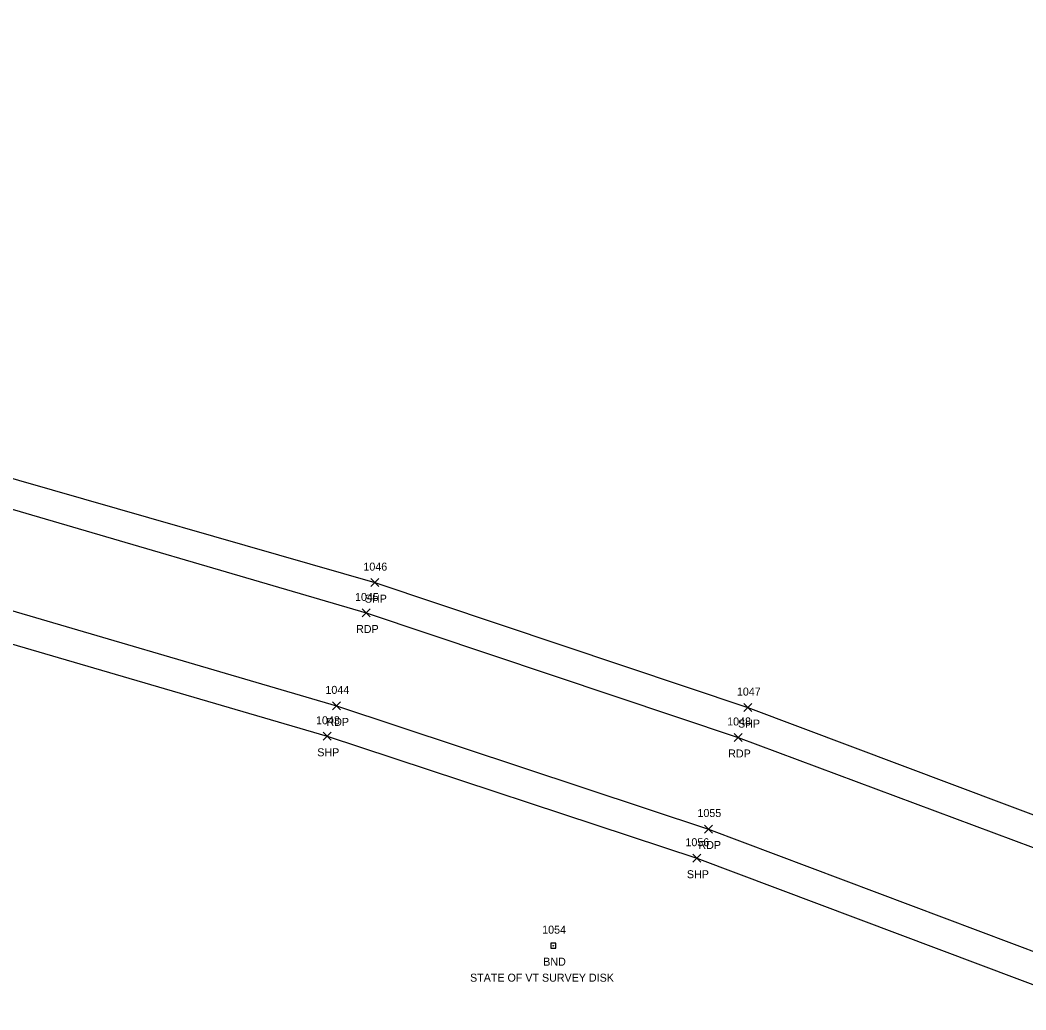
# Model space of a CAD drawing. Extents: x 1519347 to 1522636, y 378779 to 379832.
# Drawn here: x 1521349.9 to 1521601.3, y 379467.3 to 379714.6 of the extents above; entities that cross this region are included whole.
import ezdxf

# ---------------------------------------------------------------- set-up
doc = ezdxf.new("R2010")
doc.units = 0
for name, color, linetype in [('M_A', 7, 'Continuous'), ('M_C', 7, 'Continuous'), ('M_I', 7, 'Continuous'), ('MHBP', 7, 'Continuous'), ('P_A', 7, 'Continuous'), ('P_I', 7, 'Continuous'), ('P_TIC', 7, 'Continuous'), ('PE', 7, 'Continuous'), ('PSP', 7, 'Continuous')]:
    doc.layers.add(name, color=color, linetype=linetype)

msp = doc.modelspace()

# ---------------------------------------------------------------- linework, layer by layer
at = {"layer": 'MHBP'}
for p, q in [((1521483.81, 379483.95), (1521482.56, 379483.95)), ((1521482.56, 379483.95), (1521482.56, 379482.7)), ((1521483.81, 379483.95), (1521482.56, 379483.95)), ((1521482.56, 379483.95), (1521482.56, 379482.7)), ((1521483.81, 379482.7), (1521483.81, 379483.95)), ((1521483.81, 379482.7), (1521483.81, 379483.95)), ((1521482.56, 379482.7), (1521483.81, 379482.7)), ((1521482.56, 379482.7), (1521483.81, 379482.7))]:
    msp.add_line(p, q, dxfattribs=at)
msp.add_circle((1521483.16, 379483.29), 0.0833, dxfattribs=at)
at = {"layer": 'P_TIC'}
for points in [[(1521437.52, 379573.01), (1521439.52, 379575.01)], [(1521439.52, 379573.01), (1521437.52, 379575.01)], [(1521435.37, 379565.43), (1521437.37, 379567.43)], [(1521437.37, 379565.43), (1521435.37, 379567.43)], [(1521427.97, 379542.22), (1521429.97, 379544.22)], [(1521429.97, 379542.22), (1521427.97, 379544.22)], [(1521530.82, 379541.79), (1521532.82, 379543.79)], [(1521532.82, 379541.79), (1521530.82, 379543.79)], [(1521425.62, 379534.62), (1521427.62, 379536.62)], [(1521427.62, 379534.62), (1521425.62, 379536.62)], [(1521528.39, 379534.32), (1521530.39, 379536.32)], [(1521530.39, 379534.32), (1521528.39, 379536.32)], [(1521520.96, 379511.45), (1521522.96, 379513.45)], [(1521522.96, 379511.45), (1521520.96, 379513.45)], [(1521518.02, 379504.15), (1521520.02, 379506.15)], [(1521520.02, 379504.15), (1521518.02, 379506.15)]]:
    msp.add_lwpolyline(points, dxfattribs=at)
at = {"layer": 'PE'}
for points in [[(1520500.29, 379707.13), (1520597.92, 379701.55), (1520704.39, 379695.17), (1520766.67, 379691.18), (1520865.72, 379682.95), (1520944.87, 379673.83), (1521043.86, 379659.67), (1521144.22, 379641.18), (1521240.97, 379619.56), (1521339.55, 379594.81), (1521436.37, 379566.43), (1521529.39, 379535.32), (1521632.62, 379496.8)], [(1520499.12, 379683.2), (1520597.12, 379677.59), (1520702.85, 379672.1), (1520767.36, 379666.64), (1520862.37, 379658.78), (1520941.16, 379649.92), (1521039.54, 379635.66), (1521138.91, 379617.62), (1521235.57, 379596.13), (1521333.44, 379571.25), (1521428.97, 379543.22), (1521521.96, 379512.45), (1521622.97, 379474.43)]]:
    msp.add_lwpolyline(points, dxfattribs=at)
at = {"layer": 'PSP'}
for points in [[(1520500.66, 379714.58), (1520598.16, 379708.86), (1520704.83, 379702.57), (1520767.67, 379698.75), (1520866.58, 379691.1), (1520963.04, 379679.86), (1520962.98, 379679.81), (1521045.38, 379667.49), (1521145.9, 379649.23), (1521242.81, 379627.02), (1521341.58, 379601.87), (1521438.52, 379574.01), (1521531.82, 379542.79), (1521635.1, 379503.97)], [(1520498.56, 379673.83), (1520597.58, 379669.39), (1520622.82, 379668.23), (1520701.9, 379664.18), (1520764.8, 379659.6), (1520862, 379650.94), (1520940.1, 379642.46), (1521038.42, 379628.05), (1521137.18, 379609.65), (1521233.6, 379588.29), (1521331.39, 379563.44), (1521426.62, 379535.62), (1521519.02, 379505.15), (1521619.86, 379467.25)]]:
    msp.add_lwpolyline(points, dxfattribs=at)

# ---------------------------------------------------------------- texts
at = {"layer": 'M_A'}
msp.add_text('BND', height=2, dxfattribs=at).set_placement((1521480.64, 379478.3))
at = {"layer": 'M_C'}
msp.add_text('STATE OF VT SURVEY DISK', height=2, dxfattribs=at).set_placement((1521462.35, 379474.3))
at = {"layer": 'M_I'}
msp.add_text('1054', height=2, dxfattribs=at).set_placement((1521480.38, 379486.3))
at = {"layer": 'P_A'}
for s, p in [('SHP', (1521436.05, 379569.01)), ('RDP', (1521433.86, 379561.43)), ('RDP', (1521426.46, 379538.22)), ('SHP', (1521529.35, 379537.79)), ('SHP', (1521424.16, 379530.62)), ('RDP', (1521526.88, 379530.32)), ('RDP', (1521519.45, 379507.45)), ('SHP', (1521516.55, 379500.15))]:
    msp.add_text(s, height=2, dxfattribs=at).set_placement(p)
at = {"layer": 'P_I'}
for s, p in [('1046', (1521435.69, 379577.01)), ('1045', (1521433.6, 379569.43)), ('1044', (1521426.2, 379546.22)), ('1047', (1521529.05, 379545.79)), ('1043', (1521423.85, 379538.62)), ('1048', (1521526.62, 379538.32)), ('1055', (1521519.19, 379515.45)), ('1056', (1521516.19, 379508.15))]:
    msp.add_text(s, height=2, dxfattribs=at).set_placement(p)

doc.saveas('drawing.dxf')
